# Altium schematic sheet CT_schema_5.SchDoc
size 430 x 429 mm
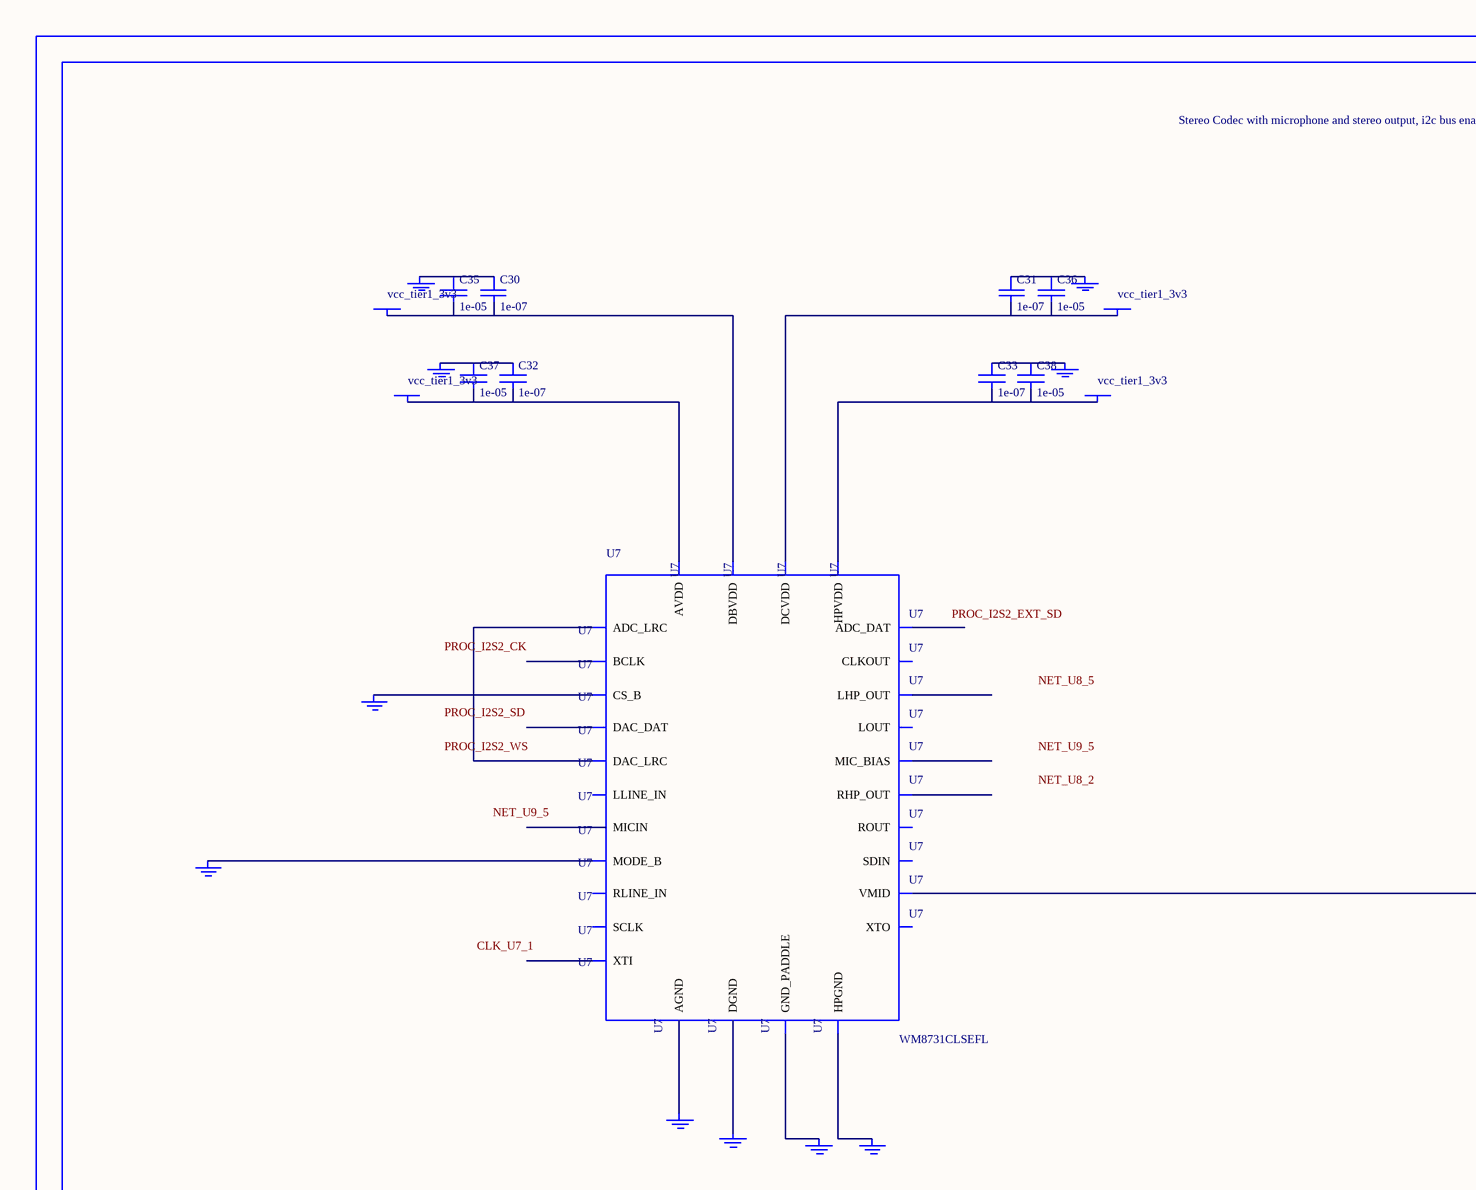
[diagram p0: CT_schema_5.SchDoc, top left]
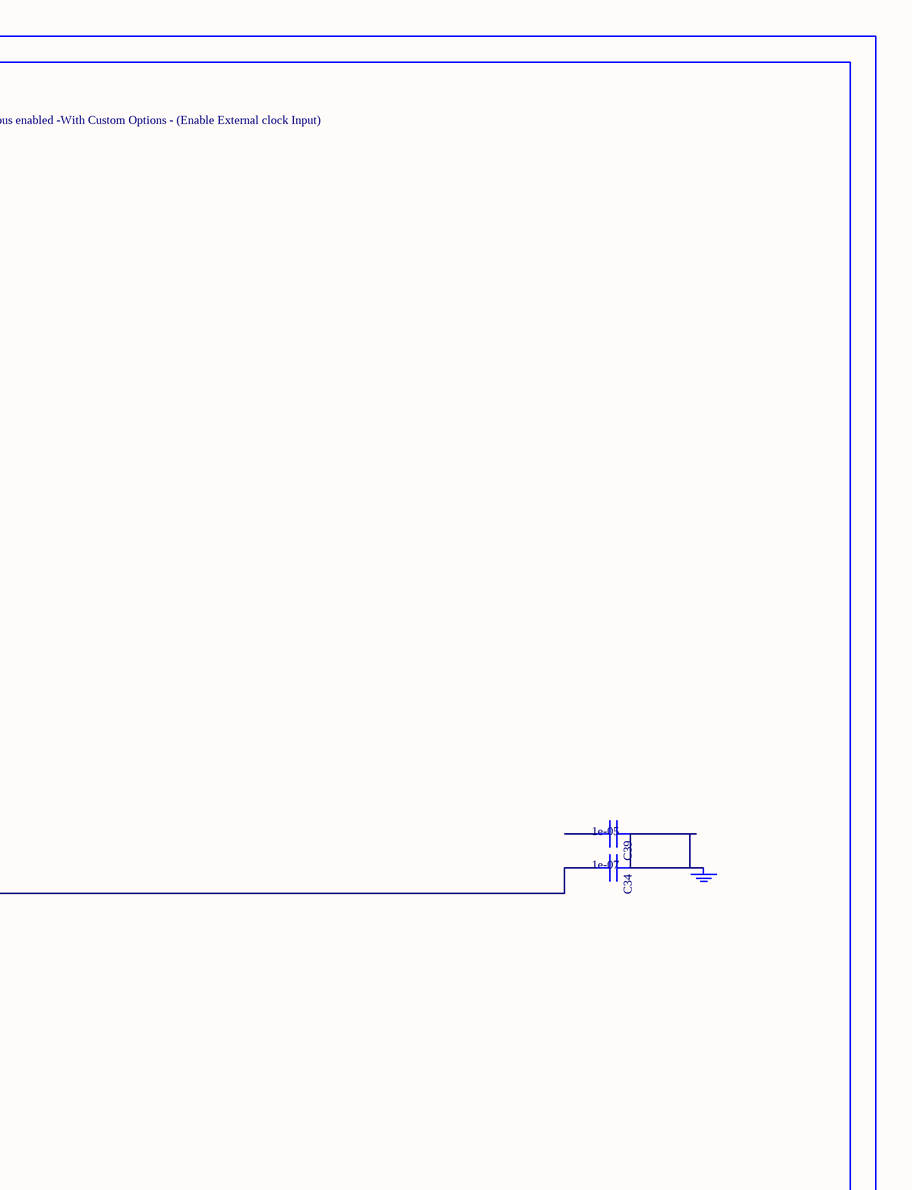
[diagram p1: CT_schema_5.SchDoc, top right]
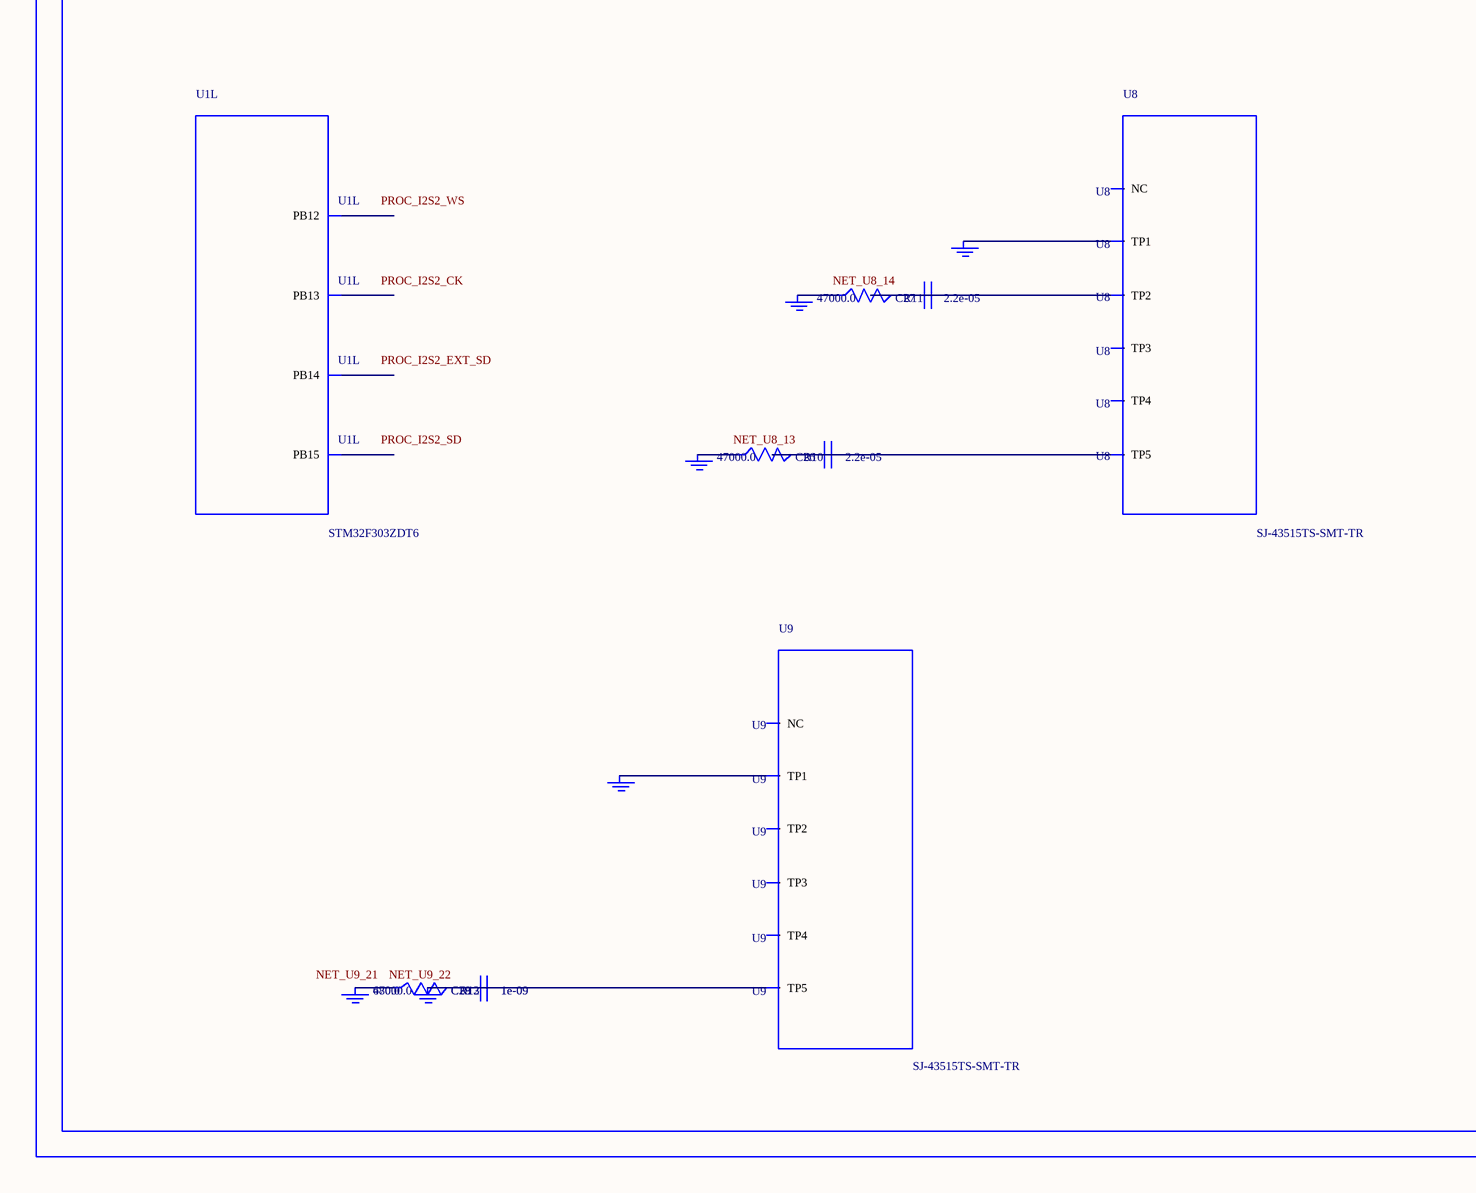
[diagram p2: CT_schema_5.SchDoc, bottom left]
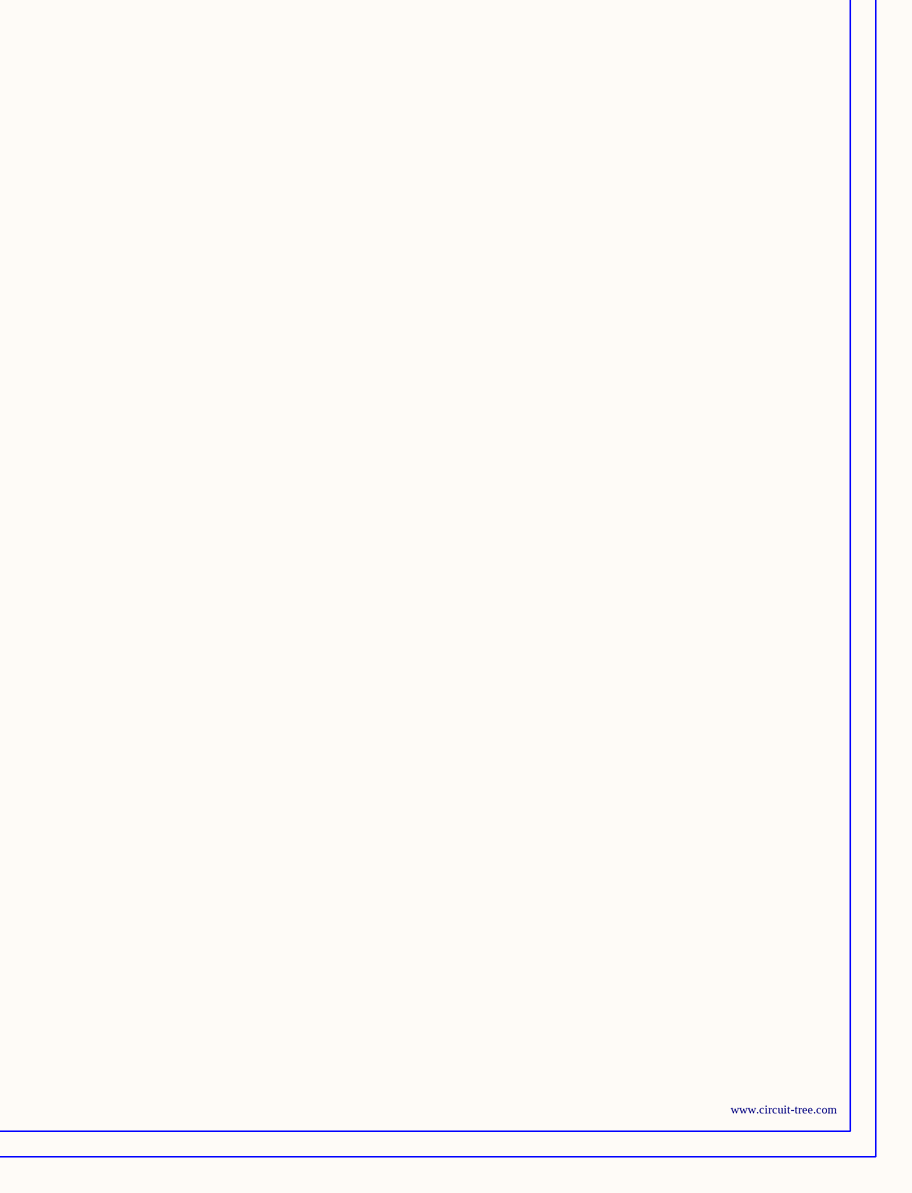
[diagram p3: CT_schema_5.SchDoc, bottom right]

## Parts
BORDER4  (no value)
C26  2.2e-05  [C1210]
C27  2.2e-05  [C1210]
C28  1e-09  [C0402]
C29  1e-09  [C0402]
C30  1e-07  [C0402]
C31  1e-07  [C0402]
C32  1e-07  [C0402]
C33  1e-07  [C0402]
C34  1e-07  [C0402]
C35  1e-05  [C0805]
C36  1e-05  [C0805]
C37  1e-05  [C0805]
C38  1e-05  [C0805]
C39  1e-05  [C0805]
GND_INSTANCE_4_0  (no value)
GND_INSTANCE_4_1  (no value)
GND_INSTANCE_4_2  (no value)
GND_INSTANCE_4_3  (no value)
GND_INSTANCE_4_4  (no value)
GND_INSTANCE_4_5  (no value)
GND_INSTANCE_4_6  (no value)
GND_INSTANCE_4_7  (no value)
GND_INSTANCE_4_8  (no value)
GND_INSTANCE_4_9  (no value)
GND_INSTANCE_4_10  (no value)
GND_INSTANCE_4_11  (no value)
GND_INSTANCE_4_12  (no value)
GND_INSTANCE_4_13  (no value)
GND_INSTANCE_4_14  (no value)
GND_INSTANCE_4_15  (no value)
GND_INSTANCE_4_16  (no value)
POWER_INSTANCE_4_0  vcc_tier1_3v3
POWER_INSTANCE_4_1  vcc_tier1_3v3
POWER_INSTANCE_4_2  vcc_tier1_3v3
POWER_INSTANCE_4_3  vcc_tier1_3v3
R10  47000.0  [R0603]
R11  47000.0  [R0603]
R12  47000.0  [R0603]
R13  680.0  [R0603]
U1  STM32F303ZDT6  [LQFP144]  (part L of 13)
U7  WM8731CLSEFL  [QFN-28]
U8  SJ-43515TS-SMT-TR  [SJ-43515TS-SMT-TR]
U9  SJ-43515TS-SMT-TR  [SJ-43515TS-SMT-TR]

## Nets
NetC26_1: C26.1 C26.2 R10.2 U8.5(TP5)
NetC27_1: C27.1 C27.2 R11.2 U8.2(TP2)
NetC28_1: C28.1 C28.2 C29.1 C29.2 GND_INSTANCE_4_16.0(GND) R12.2 R13.2 U9.5(TP5)
NetC30_1: C30.1 C35.1 GND_INSTANCE_4_1.0(GND)
NetC30_2: C30.2 C35.2 POWER_INSTANCE_4_1.0(PWR) U7.5(DBVDD)
NetC31_1: C31.1 C36.1 GND_INSTANCE_4_0.0(GND)
NetC31_2: C31.2 C36.2 POWER_INSTANCE_4_0.0(PWR) U7.3(DCVDD)
NetC32_1: C32.1 C37.1 GND_INSTANCE_4_4.0(GND)
NetC32_2: C32.2 C37.2 POWER_INSTANCE_4_3.0(PWR) U7.18(AVDD)
NetC33_1: C33.1 C38.1 GND_INSTANCE_4_2.0(GND)
NetC33_2: C33.2 C38.2 POWER_INSTANCE_4_2.0(PWR) U7.12(HPVDD)
NetC34_1: C34.1 C39.1 GND_INSTANCE_4_5.0(GND)
NetC34_2: C34.2 U7.20(VMID)
NetGND_INSTANCE_4_3_0: GND_INSTANCE_4_3.0(GND) U7.15(HPGND)
NetGND_INSTANCE_4_6_0: GND_INSTANCE_4_6.0(GND) U7.25(MODE_B)
NetGND_INSTANCE_4_7_0: GND_INSTANCE_4_7.0(GND) U7.26(CS_B)
NetGND_INSTANCE_4_8_0: GND_INSTANCE_4_8.0(GND) U7.29(GND_PADDLE)
NetGND_INSTANCE_4_9_0: GND_INSTANCE_4_9.0(GND) U7.4(DGND)
NetGND_INSTANCE_4_10_0: GND_INSTANCE_4_10.0(GND) U7.19(AGND)
NetGND_INSTANCE_4_11_0: GND_INSTANCE_4_11.0(GND) U8.1(TP1)
NetGND_INSTANCE_4_12_0: GND_INSTANCE_4_12.0(GND) R11.1
NetGND_INSTANCE_4_13_0: GND_INSTANCE_4_13.0(GND) R10.1
NetGND_INSTANCE_4_14_0: GND_INSTANCE_4_14.0(GND) U9.1(TP1)
NetGND_INSTANCE_4_15_0: GND_INSTANCE_4_15.0(GND) R12.1 R13.1
NetU7_9: U7.9(DAC_LRC) U7.11(ADC_LRC)

Not connected (* = marked no-connect by the designer): C39 2; U1 73(PB12) 74(PB13) 75(PB14) 76(PB15); U7 1(XTI) 2(XTO) 6(CLKOUT) 7(BCLK) 8(DAC_DAT) 10(ADC_DAT) 13(LHP_OUT) 14(RHP_OUT) 16(LOUT) 17(ROUT) 21(MIC_BIAS) 22(MICIN) 23(RLINE_IN) 24(LLINE_IN) 27(SDIN) 28(SCLK); U8 3(TP3) 4(TP4) 6(NC); U9 2(TP2) 3(TP3) 4(TP4) 6(NC)

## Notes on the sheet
- Labels drawn without touching a wire or pin: CLK_U7_1, NET_U8_2, NET_U8_5, NET_U8_13, NET_U8_14, NET_U9_5, NET_U9_21, NET_U9_22, PROC_I2S2_CK, PROC_I2S2_EXT_SD, PROC_I2S2_SD, PROC_I2S2_WS

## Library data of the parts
BORDER4 = BORDER_PAGE4
C26 C27 = C1210C224K5RACTU
C28 C29 = C0402C102K3RAC
C30-C34 = C0402C104K3RACTU
C35-C39 = C0805C106K8RACTU
GND_INSTANCE_4_0-GND_INSTANCE_4_16 = GND
POWER_INSTANCE_4_0-POWER_INSTANCE_4_3 = PWR
R10-R12 = RC0603JR-0747KL
R13 = RC0603JR-07680RL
